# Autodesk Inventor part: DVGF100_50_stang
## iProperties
Created: 2010-04
Part Number: DVGF100_50_stang
Document SubType Name: Modeling
Designer: TB
Mass: 803.185 g
Surface Area: 677.205 cm^2
Volume: 803.185 cm^3
Density: 1 g/cm^3
Author: TB
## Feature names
1. Revolution1
2. Fillet1
3. Revolution2
4. Extrusion1
5. Extrusion2
6. Chamfer1
7. Chamfer2
8. Fillet2
